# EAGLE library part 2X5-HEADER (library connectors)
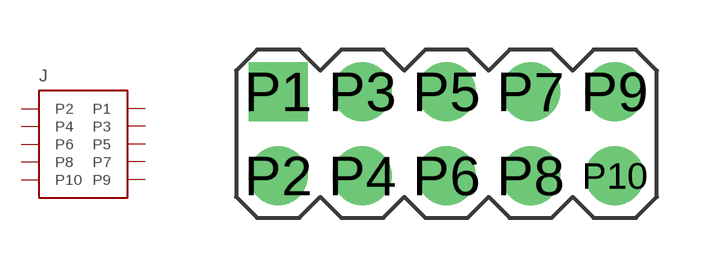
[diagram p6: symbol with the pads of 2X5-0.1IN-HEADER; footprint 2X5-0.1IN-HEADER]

Designator prefix J

## 2X5-HEADER0.1IN  [2X5-0.1IN-HEADER]
P1  P1  pas
P2  P2  pas
P3  P3  pas
P4  P4  pas
P5  P5  pas
P6  P6  pas
P7  P7  pas
P8  P8  pas
P9  P9  pas
P10  P10  pas

## Footprint 2X5-0.1IN-HEADER (pad centres in mm)
drill 1.05 pad 1.778 square: P1 -5.08,1.27
drill 1.05 pad 1.778 round: P2 -5.08,-1.27; P3 -2.54,1.27; P4 -2.54,-1.27; P5 0,1.27; P6 0,-1.27; P7 2.54,1.27; P8 2.54,-1.27; P9 5.08,1.27; P10 5.08,-1.27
